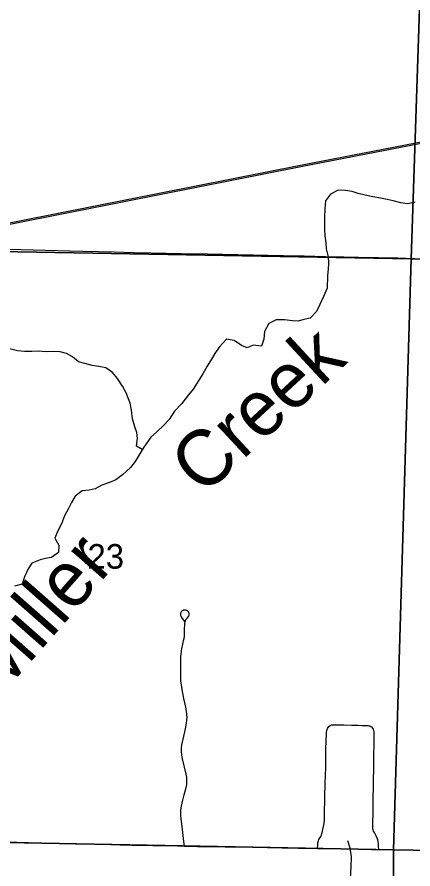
# Model space of a CAD drawing. Extents: x 0 to 34, y 0 to 22.
# Drawn here: x 5.012 to 5.686, y 18.428 to 19.878 of the extents above; entities that cross this region are included whole.
import ezdxf

# ---------------------------------------------------------------- set-up
doc = ezdxf.new("R2010")
doc.units = 0
for name, color, linetype in [('GM_X_County_Road', 7, 'Continuous'), ('GM_X_Minor_River', 7, 'Continuous'), ('GM_X_Minor_River_Text', 7, 'Continuous'), ('GM_X_Rail_Line', 7, 'Continuous'), ('GM_X_Section', 7, 'Continuous'), ('GM_X_Section_Text', 7, 'Continuous'), ('GM_X_Township_Road', 7, 'Continuous')]:
    doc.layers.add(name, color=color, linetype=linetype)

msp = doc.modelspace()

# ---------------------------------------------------------------- linework, layer by layer
at = {"layer": 'GM_X_County_Road'}
for points in [[(4.9744, 19.4836), (5.0191, 19.4825), (5.1012, 19.4803), (5.1241, 19.4797), (5.1775, 19.4783), (5.2105, 19.4775), (5.2403, 19.4769), (5.2913, 19.4758), (5.3363, 19.4748), (5.466, 19.4723), (5.5008, 19.4714), (5.5375, 19.4706), (5.5685, 19.47), (5.5934, 19.4693), (5.6605, 19.468), (5.6896, 19.4674)], [(5.5236, 18.4631), (5.5243, 18.4706), (5.5246, 18.4726), (5.5248, 18.4741), (5.5254, 18.4762), (5.5262, 18.4781), (5.5293, 18.4836), (5.5304, 18.4858), (5.5311, 18.4883), (5.5316, 18.4904), (5.5335, 18.4982), (5.5349, 18.5055), (5.5357, 18.5116), (5.5359, 18.519), (5.5364, 18.5513), (5.5368, 18.5737), (5.5378, 18.601), (5.538, 18.6151), (5.538, 18.6176), (5.538, 18.6194), (5.5381, 18.6311), (5.5386, 18.6473), (5.539, 18.656), (5.5392, 18.6603), (5.5396, 18.6636), (5.5401, 18.6656), (5.5408, 18.6674), (5.5418, 18.6691), (5.5431, 18.6708)], [(5.5431, 18.6708), (5.5451, 18.6724), (5.5464, 18.673), (5.5476, 18.6733), (5.5502, 18.6736), (5.554, 18.6737), (5.5583, 18.6736), (5.5689, 18.6733), (5.5821, 18.673), (5.5928, 18.6728), (5.5996, 18.6726), (5.6058, 18.6725), (5.6076, 18.6723), (5.6096, 18.6722), (5.6112, 18.6718), (5.6128, 18.6715), (5.6146, 18.6708), (5.6158, 18.6701), (5.6169, 18.6693)], [(5.6284, 18.4612), (5.6279, 18.4662), (5.6276, 18.4706), (5.627, 18.475), (5.6263, 18.478), (5.6255, 18.4805), (5.6237, 18.4845), (5.6207, 18.49), (5.6193, 18.4927), (5.6186, 18.4949), (5.6183, 18.4966), (5.6182, 18.5016), (5.6182, 18.5095), (5.6184, 18.5202), (5.6185, 18.5287), (5.6184, 18.5399), (5.6185, 18.5455), (5.6186, 18.5485), (5.6187, 18.5547), (5.6189, 18.5621), (5.6193, 18.5794), (5.6198, 18.5992), (5.6199, 18.6123), (5.62, 18.6241), (5.6201, 18.639), (5.6202, 18.6452), (5.6205, 18.6551), (5.6205, 18.6589), (5.6203, 18.6615), (5.6198, 18.6641), (5.6189, 18.6663), (5.618, 18.6679), (5.6169, 18.6693)], [(4.6695, 18.4812), (4.6983, 18.4807), (4.7206, 18.4801), (4.7492, 18.4796), (4.7809, 18.4789), (4.8213, 18.4778), (4.8455, 18.4772), (4.8741, 18.4767), (4.9065, 18.476), (4.94, 18.4752), (4.973, 18.4744), (5.0115, 18.4737), (5.0521, 18.4726), (5.0836, 18.4718), (5.1116, 18.4712), (5.1308, 18.4708), (5.1559, 18.4701), (5.1868, 18.4693), (5.2073, 18.4689), (5.2433, 18.4682), (5.2856, 18.4673), (5.297, 18.4671)], [(5.297, 18.4671), (5.3192, 18.4666), (5.413, 18.465), (5.4634, 18.4642), (5.4913, 18.4637), (5.5236, 18.4631)], [(5.5236, 18.4631), (5.5317, 18.4629), (5.5758, 18.4623), (5.6156, 18.4614), (5.6284, 18.4612)], [(5.6284, 18.4612), (5.6311, 18.4612), (5.6952, 18.4603), (5.7352, 18.4597), (5.7959, 18.4588), (5.822, 18.4584), (5.8792, 18.4573), (5.9028, 18.457), (5.9413, 18.4565), (5.9699, 18.4558), (6.0085, 18.4551), (6.0377, 18.4547), (6.0824, 18.4541), (6.1209, 18.4535), (6.1433, 18.453), (6.1714, 18.4521)]]:
    msp.add_lwpolyline(points, dxfattribs=at)
at = {"layer": 'GM_X_Minor_River'}
for points in [[(5.6899, 19.5628), (5.677, 19.5604), (5.666, 19.5618), (5.6528, 19.5651), (5.6426, 19.5675), (5.6313, 19.5697), (5.6181, 19.5718), (5.6052, 19.5747), (5.5932, 19.578), (5.583, 19.5812), (5.5716, 19.5826), (5.5587, 19.5832), (5.5457, 19.5766), (5.5376, 19.5654), (5.5365, 19.5514), (5.5355, 19.537), (5.5357, 19.5275), (5.5355, 19.5169), (5.536, 19.5055), (5.5377, 19.494), (5.5386, 19.4834), (5.5418, 19.4701), (5.5427, 19.4594), (5.5421, 19.4492), (5.5408, 19.4382), (5.5404, 19.4169), (5.534, 19.4023), (5.5277, 19.3891), (5.5218, 19.3767), (5.5113, 19.3655), (5.5007, 19.3631), (5.4908, 19.3606), (5.4813, 19.3608), (5.4673, 19.3626), (5.4533, 19.3628), (5.4406, 19.3566), (5.4332, 19.3431), (5.4325, 19.3298), (5.4281, 19.3178), (5.4141, 19.3199), (5.4042, 19.3152), (5.3944, 19.3188), (5.3817, 19.3274), (5.3688, 19.3299), (5.3564, 19.3161), (5.3486, 19.3057), (5.3431, 19.2959), (5.3357, 19.2839), (5.3286, 19.2711), (5.3122, 19.2449), (5.304, 19.2352), (5.2924, 19.2202), (5.2804, 19.2075), (5.271, 19.1933), (5.2621, 19.1832), (5.2497, 19.1717), (5.2397, 19.1628), (5.228, 19.1463), (5.2217, 19.1358), (5.2131, 19.1219), (5.2053, 19.1114), (5.1918, 19.0988), (5.1803, 19.0903), (5.1696, 19.086), (5.1566, 19.0816), (5.1447, 19.0754), (5.1348, 19.073), (5.123, 19.0717), (5.1107, 19.0624), (5.1045, 19.0519), (5.0993, 19.0414), (5.0926, 19.029), (5.0878, 19.0154), (5.0815, 19.0038), (5.076, 18.991), (5.083, 18.9791), (5.0827, 18.9669), (5.0704, 18.9581), (5.0605, 18.9567), (5.051, 18.9543), (5.0372, 18.9488), (5.0306, 18.9387), (5.0243, 18.9256), (5.0206, 18.9131), (5.0077, 18.9092)], [(5.2253, 19.1419), (5.2151, 19.1477), (5.2173, 19.1606), (5.216, 19.1712), (5.2124, 19.1808), (5.2085, 19.1945), (5.2068, 19.209), (5.2044, 19.2211), (5.1975, 19.2384), (5.1917, 19.2499), (5.1828, 19.2629), (5.1747, 19.273), (5.1631, 19.2808), (5.151, 19.2833), (5.1397, 19.285), (5.1272, 19.2883), (5.1163, 19.2915), (5.1062, 19.2997), (5.0961, 19.3056), (5.0851, 19.3085), (5.0719, 19.3091), (5.0612, 19.3085), (5.048, 19.3092), (5.037, 19.309), (5.0248, 19.3089), (5.0127, 19.3102), (4.9942, 19.3144)], [(5.5798, 18.4121), (5.5809, 18.4318), (5.5816, 18.4488), (5.5792, 18.4633), (5.5753, 18.4759)]]:
    msp.add_lwpolyline(points, dxfattribs=at)
at = {"layer": 'GM_X_Rail_Line'}
for points in [[(2.1, 18.9599), (2.5738, 19.0523), (3.1234, 19.1602), (3.6767, 19.2666), (4.2609, 19.3838), (4.9006, 19.5087), (5.4948, 19.6259), (6.096, 19.7423), (6.7148, 19.8649), (7.2736, 19.9767), (7.8416, 20.0877), (8.2886, 20.1741), (8.3633, 20.1886), (8.9, 20.2933)], [(2.1, 18.9575), (2.5743, 19.05), (3.1238, 19.158), (3.6772, 19.2644), (4.2614, 19.3816), (4.9011, 19.5065), (5.4953, 19.6236), (6.0964, 19.7401), (6.7153, 19.8626), (7.2741, 19.9744), (7.8421, 20.0855), (8.2891, 20.1718), (8.3637, 20.1864), (8.9, 20.2909)]]:
    msp.add_lwpolyline(points, dxfattribs=at)
at = {"layer": 'GM_X_Section'}
for points in [[(4.6829, 20.4926), (5.7169, 20.4716), (5.6833, 19.4667), (4.6614, 19.4847)], [(5.7169, 20.4716), (6.7143, 20.4382), (6.6979, 19.4726), (6.6975, 19.4397), (5.6833, 19.4667)], [(4.6614, 19.4847), (5.6833, 19.4667), (5.6535, 18.4609), (4.6642, 18.4797)], [(5.6833, 19.4667), (6.6975, 19.4397), (6.6853, 18.443), (5.6535, 18.4609)], [(4.6642, 18.4797), (5.6535, 18.4609), (5.6551, 17.4555), (4.6605, 17.4748)], [(5.6535, 18.4609), (6.6853, 18.443), (6.6654, 17.4415), (5.6551, 17.4555)]]:
    msp.add_lwpolyline(points, close=True, dxfattribs=at)
at = {"layer": 'GM_X_Township_Road'}
msp.add_lwpolyline([(5.297, 18.4671), (5.2961, 18.475), (5.2942, 18.4904), (5.2918, 18.5095), (5.2911, 18.5182), (5.2909, 18.5239), (5.2912, 18.5289), (5.2921, 18.5352), (5.2937, 18.5431), (5.2966, 18.5546), (5.2998, 18.5666), (5.3009, 18.5721), (5.3014, 18.5763), (5.3014, 18.5805), (5.3011, 18.5842), (5.3002, 18.5896), (5.2939, 18.6156), (5.2926, 18.6224), (5.292, 18.628), (5.2921, 18.6337), (5.2928, 18.6394), (5.2948, 18.6492), (5.2988, 18.6668), (5.3006, 18.6765), (5.3013, 18.682), (5.3016, 18.6862), (5.3014, 18.6911), (5.3007, 18.6966), (5.2994, 18.7033), (5.296, 18.7184), (5.293, 18.7337), (5.2918, 18.7418), (5.2912, 18.748), (5.2908, 18.758), (5.2907, 18.7698), (5.2908, 18.7835), (5.2909, 18.7885), (5.2915, 18.7948), (5.2919, 18.7972), (5.2923, 18.7997), (5.2951, 18.8135), (5.2957, 18.8169), (5.2965, 18.8202), (5.297, 18.8243), (5.2972, 18.8278), (5.2973, 18.8324), (5.2974, 18.8364), (5.2977, 18.844), (5.2979, 18.8467), (5.2984, 18.8491), (5.2987, 18.8506), (5.299, 18.8516), (5.2996, 18.8527), (5.3001, 18.8533), (5.3022, 18.8558), (5.304, 18.8581), (5.3046, 18.8592), (5.3049, 18.8601), (5.305, 18.8609), (5.305, 18.8617), (5.3049, 18.8633), (5.3043, 18.8649), (5.304, 18.8656), (5.3034, 18.8663), (5.303, 18.8668), (5.3023, 18.8674), (5.3016, 18.8679), (5.3009, 18.8683), (5.2993, 18.8688), (5.2986, 18.8689), (5.2976, 18.8689), (5.296, 18.8687), (5.2951, 18.8684), (5.2944, 18.8681), (5.293, 18.8673), (5.2923, 18.8667), (5.2919, 18.8661), (5.2914, 18.8655), (5.291, 18.8647), (5.2905, 18.8635), (5.2903, 18.8626), (5.2902, 18.861), (5.2904, 18.8593), (5.2914, 18.8573), (5.2934, 18.8542), (5.2976, 18.8488)], dxfattribs=at)

# ---------------------------------------------------------------- texts
at = {"layer": 'GM_X_Minor_River_Text'}
for s, rotation, p in [('Creek', 42.7839, (5.3287, 19.0612)), ('Miller', 48.7053, (4.9812, 18.7189))]:
    msp.add_text(s, height=0.09477, rotation=rotation, dxfattribs=at).set_placement(p)
at = {"layer": 'GM_X_Section_Text'}
msp.add_text('23', height=0.04186, rotation=0, dxfattribs=at).set_placement((5.1319, 18.9392))

doc.saveas('drawing.dxf')
